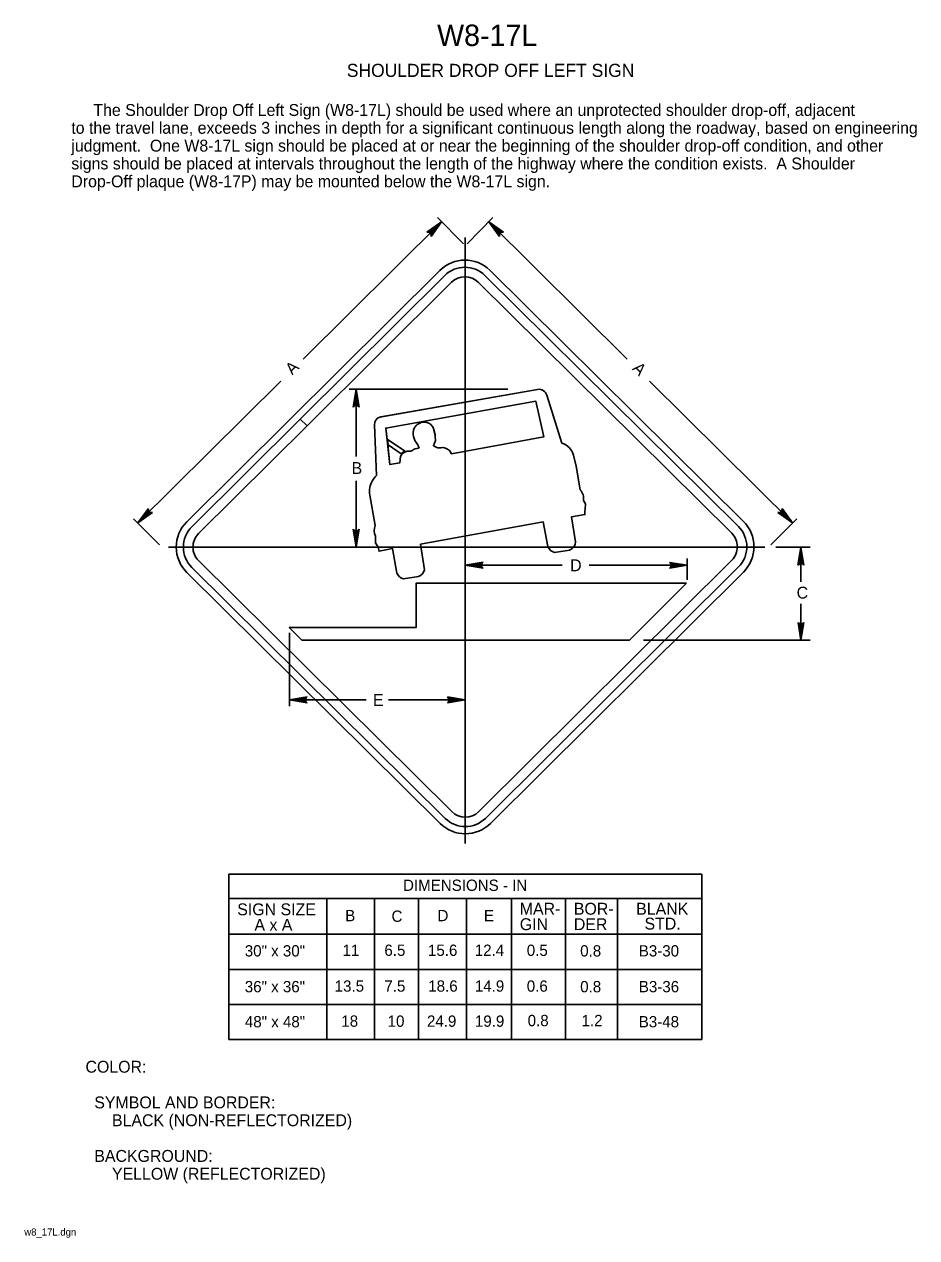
# Model space of a CAD drawing. Extents: x 0.013 to 0.2, y 0.004 to 0.259.
import ezdxf

# ---------------------------------------------------------------- set-up
doc = ezdxf.new("R2010")
doc.units = 0
for name, color, linetype in [('1', 7, 'Continuous'), ('2', 7, 'Continuous'), ('3', 7, 'Continuous')]:
    doc.layers.add(name, color=color, linetype=linetype)

# ---------------------------------------------------------------- blocks, each defined once
blk = doc.blocks.new('RARROW')
at = {"layer": '3'}
for p, q in [((-2.156, 0.28500000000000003), (-2.2665, 0.384625)), ((-2.2665, 0.384625), (0, 0)), ((0, 0), (-2.2665, -0.379125)), ((-2.156, 0.28500000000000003), (-2.075625, 0.12075)), ((0, 0), (-2.156, 0.28500000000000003)), ((-2.14975, -0.2705), (0, 0)), ((-2.075625, 0.12075), (0, 0)), ((0, 0), (-2.074, -0.108)), ((-2.2665, -0.379125), (-2.14975, -0.2705)), ((-2.074, -0.108), (-2.14975, -0.2705))]:
    blk.add_line(p, q, dxfattribs=at)

msp = doc.modelspace()

# ---------------------------------------------------------------- linework, layer by layer
at = {"layer": '1'}
for p, q in [((0.1053605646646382, 0.21425714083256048), (0.1053605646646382, 0.08680598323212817)), ((0.07068008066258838, 0.17605027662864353), (0.10107444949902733, 0.2062433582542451)), ((0.10248395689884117, 0.20482445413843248), (0.07210136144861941, 0.17464306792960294)), ((0.16141532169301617, 0.1520587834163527), (0.10811729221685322, 0.2048291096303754)), ((0.10952445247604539, 0.20625034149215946), (0.16282248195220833, 0.15348001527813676)), ((0.08742460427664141, 0.17645826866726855), (0.12056955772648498, 0.18228091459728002)), ((0.1225392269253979, 0.1810833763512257), (0.12567791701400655, 0.1710036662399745)), ((0.04786371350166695, 0.15338501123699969), (0.07068008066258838, 0.17605027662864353)), ((0.07068008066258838, 0.17605027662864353), (0.07210136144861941, 0.17464306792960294)), ((0.07210136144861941, 0.17464306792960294), (0.07068008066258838, 0.17605027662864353)), ((0.07210136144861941, 0.17464306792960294), (0.049273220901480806, 0.15196610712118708)), ((0.08667658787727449, 0.16417888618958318), (0.08630062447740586, 0.17482561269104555)), ((0.08915051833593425, 0.17063020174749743), (0.08900977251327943, 0.17178997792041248)), ((0.08900977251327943, 0.17178997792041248), (0.0927147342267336, 0.16929882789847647)), ((0.12191549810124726, 0.17232388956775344), (0.10245110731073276, 0.16876716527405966)), ((0.09190937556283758, 0.16875870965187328), (0.08915051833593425, 0.17063020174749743)), ((0.09416894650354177, 0.16939378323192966), (0.09393171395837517, 0.16930810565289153)), ((0.09532173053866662, 0.17080843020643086), (0.09564590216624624, 0.16991083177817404)), ((0.09940903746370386, 0.17006046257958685), (0.09866722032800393, 0.17043551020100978)), ((0.10245110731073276, 0.16876716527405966), (0.10204736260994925, 0.16943059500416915)), ((0.12811941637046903, 0.1684608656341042), (0.12871538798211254, 0.16614381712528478)), ((0.12871538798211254, 0.16614381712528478), (0.12954931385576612, 0.16118168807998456)), ((0.08640088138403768, 0.15367627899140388), (0.08526974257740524, 0.16007559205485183)), ((0.12178798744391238, 0.1544280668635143), (0.09593277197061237, 0.14978453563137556)), ((0.12277516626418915, 0.14925470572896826), (0.12178798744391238, 0.1544280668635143)), ((0.042952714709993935, 0.1491282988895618), (0.16834832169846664, 0.1491282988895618)), ((0.09593277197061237, 0.14978453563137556), (0.09676872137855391, 0.14432194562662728)), ((0.12727965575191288, 0.1485103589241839), (0.12417716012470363, 0.14802723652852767)), ((0.04927791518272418, 0.14628583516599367), (0.10257594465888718, 0.09351550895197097)), ((0.10820927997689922, 0.0935201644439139), (0.16142001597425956, 0.14637851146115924)), ((0.10116878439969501, 0.09209427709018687), (0.04787075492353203, 0.1448646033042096)), ((0.09551573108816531, 0.1429306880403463), (0.09241323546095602, 0.14244756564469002)), ((0.16282952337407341, 0.14495960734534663), (0.10961878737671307, 0.09210126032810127))]:
    msp.add_line(p, q, dxfattribs=at)
for points in [[(0.12056955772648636, 0.18228091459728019), (0.08762586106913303, 0.17649362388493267), (0.08762589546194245, 0.1764934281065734), (0.0876230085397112, 0.1764931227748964), (0.08742460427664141, 0.1764582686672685)], [(0.09164332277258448, 0.16687193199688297), (0.0895269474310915, 0.1665008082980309), (0.08865805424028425, 0.1741648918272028), (0.12022784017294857, 0.1797904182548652), (0.12191549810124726, 0.17232388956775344)], [(0.09177016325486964, 0.1681814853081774), (0.09164332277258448, 0.16687193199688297), (0.0895269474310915, 0.1665008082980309), (0.08905995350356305, 0.1706199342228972), (0.08892834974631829, 0.17178074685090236), (0.08865805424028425, 0.1741648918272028), (0.12022784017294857, 0.1797904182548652), (0.12191549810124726, 0.17232388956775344), (0.10245110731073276, 0.16876716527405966), (0.10204736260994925, 0.16943059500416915)], [(0.12567791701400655, 0.17100366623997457), (0.12253922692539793, 0.1810833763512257)], [(0.08630062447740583, 0.17482561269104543), (0.08667658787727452, 0.16417888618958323)], [(0.09866722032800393, 0.17043551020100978), (0.099125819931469, 0.1715678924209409), (0.0990109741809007, 0.1723614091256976), (0.09907033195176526, 0.17273816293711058), (0.0987450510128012, 0.1739024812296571)], [(0.09940903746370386, 0.1700604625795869), (0.09866722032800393, 0.17043551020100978), (0.099125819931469, 0.1715678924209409), (0.0990109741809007, 0.1723614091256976), (0.09907033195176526, 0.17273816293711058), (0.09886476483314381, 0.17347397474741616), (0.0987450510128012, 0.1739024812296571)], [(0.09271473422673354, 0.16929882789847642), (0.08900977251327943, 0.17178997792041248), (0.08915051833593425, 0.17063020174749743), (0.09190937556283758, 0.16875870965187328)], [(0.0941689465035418, 0.16939378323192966), (0.09393171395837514, 0.16930810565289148)], [(0.09532173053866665, 0.1708084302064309), (0.09564590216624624, 0.16991083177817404)], [(0.12954931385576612, 0.16118168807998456), (0.12871538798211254, 0.16614381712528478), (0.12811941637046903, 0.1684608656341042)], [(0.09177016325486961, 0.1681814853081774), (0.09164174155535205, 0.1668809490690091)], [(0.08526974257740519, 0.16007559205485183), (0.08640088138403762, 0.15367627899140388)], [(0.13026041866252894, 0.15891250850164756), (0.1306328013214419, 0.15822212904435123), (0.13060219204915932, 0.15710398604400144), (0.13049077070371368, 0.15672384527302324), (0.13052973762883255, 0.1559680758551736), (0.1276898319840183, 0.1554732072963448), (0.1285725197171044, 0.1502112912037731)], [(0.12857251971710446, 0.15021129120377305), (0.1276898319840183, 0.1554732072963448), (0.13052973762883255, 0.1559680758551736), (0.13049077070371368, 0.15672384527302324), (0.13060219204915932, 0.15710398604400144), (0.1306328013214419, 0.15822212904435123), (0.13026041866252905, 0.15891250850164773)], [(0.09593277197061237, 0.14978453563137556), (0.12178798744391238, 0.1544280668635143), (0.12277516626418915, 0.1492547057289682)], [(0.09101124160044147, 0.1436750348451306), (0.09008030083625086, 0.14882559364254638), (0.08725567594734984, 0.1482498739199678), (0.08707744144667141, 0.14912433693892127), (0.0864759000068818, 0.15004057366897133), (0.0864759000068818, 0.15145183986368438)], [(0.0864759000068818, 0.15145183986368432), (0.0864759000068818, 0.15004057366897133), (0.08707744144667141, 0.14912433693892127), (0.08725567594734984, 0.1482498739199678), (0.09008030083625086, 0.14882559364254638), (0.0910112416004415, 0.1436750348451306)], [(0.09676872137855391, 0.14432194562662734), (0.09593277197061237, 0.14978453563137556)], [(0.12417716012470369, 0.14802723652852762), (0.12727965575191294, 0.14851035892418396)], [(0.09241323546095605, 0.14244756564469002), (0.09551573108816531, 0.14293068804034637)], [(0.1518832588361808, 0.14154188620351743), (0.09502367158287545, 0.14154188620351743), (0.09502367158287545, 0.1322096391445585), (0.06836508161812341, 0.1322096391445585), (0.07102188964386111, 0.129568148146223), (0.13991300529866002, 0.12957093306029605), (0.1518832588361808, 0.14154188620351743)], [(0.1518832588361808, 0.14154188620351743), (0.13991300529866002, 0.12957093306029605), (0.07102188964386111, 0.129568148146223), (0.06836508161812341, 0.1322096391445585), (0.09502367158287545, 0.1322096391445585), (0.09502367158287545, 0.14154188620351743), (0.1518832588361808, 0.14154188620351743)]]:
    msp.add_lwpolyline(points, dxfattribs=at)
for centre, radius, start, end in [((0.10530297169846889, 0.20198664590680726), 0.005999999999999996, 45.285051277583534, 134.8096492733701), ((0.10530297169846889, 0.20198664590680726), 0.004000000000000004, 45.285051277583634, 134.80964927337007), ((0.12087692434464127, 0.18056786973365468), 0.0017404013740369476, 17.229499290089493, 100.17217419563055), ((0.12087692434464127, 0.18056786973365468), 0.0017404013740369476, 17.229499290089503, 100.17217419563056), ((0.08778138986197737, 0.1750094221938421), 0.0014921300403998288, 103.83411158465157, 187.07601051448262), ((0.08778138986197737, 0.1750094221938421), 0.0014921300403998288, 103.83411158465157, 187.07601051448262), ((0.09752020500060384, 0.17299703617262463), 0.003102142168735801, 158.1835378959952, 224.87111651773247), ((0.09752020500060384, 0.17299703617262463), 0.0031021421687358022, 158.1835378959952, 224.87111651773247), ((0.09678454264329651, 0.17298383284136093), 0.002440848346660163, 90.66413138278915, 151.46274562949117), ((0.09678454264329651, 0.17298383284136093), 0.002440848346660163, 90.66413138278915, 151.46274562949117), ((0.09666928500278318, 0.17316791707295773), 0.0022582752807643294, 36.5300670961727, 87.79300552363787), ((0.09666928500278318, 0.17316791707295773), 0.0022582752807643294, 36.5300670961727, 87.79300552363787), ((0.09477268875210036, 0.17256172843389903), 0.004192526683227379, 12.567443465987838, 27.72395795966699), ((0.09477268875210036, 0.17256172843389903), 0.004192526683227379, 18.650581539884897, 27.723957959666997), ((0.12457428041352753, 0.16750047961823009), 0.0036729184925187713, 15.15775744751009, 72.51359655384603), ((0.12457428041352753, 0.16750047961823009), 0.003672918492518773, 15.157757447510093, 72.51359655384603), ((0.09307092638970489, 0.16780186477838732), 0.0013550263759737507, 118.82030868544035, 163.73040696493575), ((0.09307092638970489, 0.16780186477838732), 0.0013550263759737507, 118.82030868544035, 163.73040696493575), ((0.09307092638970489, 0.16780186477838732), 0.001504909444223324, 118.90139087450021, 140.51949909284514), ((0.09307092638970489, 0.16780186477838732), 0.001504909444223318, 118.90139087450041, 140.5194990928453), ((0.093650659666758, 0.16689009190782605), 0.002584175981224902, 111.23386621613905, 120.38409399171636), ((0.093650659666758, 0.16689009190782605), 0.002584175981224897, 111.2338662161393, 120.3840939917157), ((0.093650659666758, 0.16689009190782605), 0.0024342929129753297, 83.37005939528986, 120.43025837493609), ((0.093650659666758, 0.16689009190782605), 0.0024342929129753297, 83.37005939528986, 120.43025837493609), ((0.09555652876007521, 0.16779813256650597), 0.0021145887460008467, 87.57766385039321, 131.01031243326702), ((0.09555652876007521, 0.16779813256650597), 0.0021145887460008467, 87.57766385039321, 131.01031243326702), ((0.09989996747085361, 0.17159391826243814), 0.0016101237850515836, 252.24773023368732, 282.30135138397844), ((0.09989996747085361, 0.17159391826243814), 0.0016101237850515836, 252.24773023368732, 282.30135138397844), ((0.10059116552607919, 0.16803183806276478), 0.0020191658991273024, 43.84739517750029, 102.03392138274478), ((0.10059116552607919, 0.16803183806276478), 0.0020191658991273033, 43.84739517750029, 99.92887190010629), ((0.0896948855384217, 0.16092984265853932), 0.004434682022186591, 132.89148295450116, 170.84487329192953), ((0.0896948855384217, 0.16092984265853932), 0.0044346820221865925, 132.89148295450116, 170.84487329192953), ((0.09084512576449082, 0.16068839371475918), 0.005608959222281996, 170.27935181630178, 186.27231814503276), ((0.09084512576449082, 0.16068839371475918), 0.005608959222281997, 170.27935181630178, 186.27231814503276), ((0.1272505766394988, 0.15921530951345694), 0.003025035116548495, 354.2551662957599, 40.544237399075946), ((0.1272505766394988, 0.15921530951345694), 0.0030250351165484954, 354.25516629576, 40.54423739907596), ((0.05209223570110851, 0.14912829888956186), 0.006000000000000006, 134.80964927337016, 225.28505127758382), ((0.08924969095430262, 0.1526588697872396), 0.0030250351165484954, 160.34658236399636, 203.51652360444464), ((0.08924969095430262, 0.1526588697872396), 0.0030250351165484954, 160.34658236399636, 203.51652360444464), ((0.15860100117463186, 0.1492163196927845), 0.006000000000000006, 314.8096492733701, 45.285051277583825), ((0.05209223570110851, 0.14912829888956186), 0.004000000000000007, 134.80964927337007, 225.28505127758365), ((0.15860100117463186, 0.1492163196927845), 0.0040000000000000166, 314.8096492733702, 45.28505127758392), ((0.12454343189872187, 0.14985998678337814), 0.0018689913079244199, 198.8961834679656, 258.6984327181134), ((0.12454343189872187, 0.14985998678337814), 0.00186899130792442, 198.8961834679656, 258.6984327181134), ((0.12669647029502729, 0.1502954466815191), 0.0018779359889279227, 288.09213636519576, 357.4315583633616), ((0.12669647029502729, 0.1502954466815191), 0.0018779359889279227, 288.09213636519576, 357.4315583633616), ((0.09277950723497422, 0.14428031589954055), 0.0018689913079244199, 198.8961834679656, 258.6984327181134), ((0.09277950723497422, 0.14428031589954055), 0.00186899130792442, 198.8961834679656, 258.6984327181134), ((0.09493254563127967, 0.1447157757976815), 0.0018779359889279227, 288.09213636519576, 347.89438561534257), ((0.09493254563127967, 0.1447157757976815), 0.0018779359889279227, 288.09213636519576, 347.89438561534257), ((0.1053902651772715, 0.09635797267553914), 0.006000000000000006, 225.28505127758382, 314.8096492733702), ((0.1053902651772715, 0.09635797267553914), 0.003999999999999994, 225.28505127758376, 314.8096492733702)]:
    msp.add_arc(centre, radius, start, end, dxfattribs=at)
at = {"layer": '3'}
for p, q in [((0.0712652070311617, 0.18866258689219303), (0.10039481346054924, 0.21753592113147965)), ((0.10497065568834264, 0.2129194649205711), (0.09951484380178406, 0.21842370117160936)), ((0.10575047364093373, 0.2129194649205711), (0.11120628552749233, 0.21842370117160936)), ((0.13945592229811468, 0.18866258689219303), (0.11032631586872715, 0.21753592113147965)), ((0.04680658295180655, 0.15444918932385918), (0.10001731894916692, 0.2073075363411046)), ((0.1105798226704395, 0.20731626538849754), (0.16387785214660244, 0.15454593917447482)), ((0.06661774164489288, 0.18405600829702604), (0.0365011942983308, 0.15420441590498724)), ((0.14410338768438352, 0.18405600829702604), (0.17421993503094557, 0.15420441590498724)), ((0.08096905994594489, 0.1823108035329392), (0.11436272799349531, 0.1823108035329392)), ((0.08243096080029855, 0.168166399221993), (0.08243096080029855, 0.18231080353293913)), ((0.08243096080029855, 0.16307330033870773), (0.08243096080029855, 0.14913548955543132)), ((0.04107703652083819, 0.1495879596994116), (0.035621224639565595, 0.15509219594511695)), ((0.1696440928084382, 0.1495879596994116), (0.1750999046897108, 0.15509219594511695)), ((0.17072446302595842, 0.1491282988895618), (0.1779116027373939, 0.1491282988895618)), ((0.17597973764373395, 0.14181023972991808), (0.17597973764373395, 0.14907355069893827)), ((0.15207602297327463, 0.14224655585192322), (0.15207602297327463, 0.14671242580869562)), ((0.046815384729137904, 0.14379867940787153), (0.1001134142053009, 0.09102835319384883)), ((0.12575947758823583, 0.14530743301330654), (0.10538708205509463, 0.14530743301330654)), ((0.11067591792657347, 0.09103708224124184), (0.16388665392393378, 0.1438954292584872)), ((0.13142962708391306, 0.14530743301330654), (0.15207602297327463, 0.14530743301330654)), ((0.17597973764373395, 0.13721892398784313), (0.17597973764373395, 0.1295541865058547)), ((0.06837785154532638, 0.11570222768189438), (0.06837785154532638, 0.13111637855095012)), ((0.14284362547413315, 0.129568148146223), (0.1779116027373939, 0.129568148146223)), ((0.0845332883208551, 0.11700686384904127), (0.06837785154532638, 0.11700686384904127)), ((0.08922496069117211, 0.11700686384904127), (0.10535728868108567, 0.11700686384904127)), ((0.05561963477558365, 0.08034473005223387), (0.15510740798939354, 0.08034473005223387)), ((0.05561963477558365, 0.08034473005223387), (0.05561963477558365, 0.045594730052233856)), ((0.15510740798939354, 0.08034473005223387), (0.15510740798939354, 0.045594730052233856)), ((0.15510740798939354, 0.07521867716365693), (0.05561963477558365, 0.07521867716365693)), ((0.07624242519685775, 0.07521867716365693), (0.07624242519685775, 0.045594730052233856)), ((0.0955585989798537, 0.07521867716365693), (0.0955585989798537, 0.045594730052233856)), ((0.12649030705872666, 0.07521867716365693), (0.12649030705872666, 0.045594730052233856)), ((0.13742347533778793, 0.07521867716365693), (0.13742347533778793, 0.045594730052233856)), ((0.05561963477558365, 0.06771973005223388), (0.15510740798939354, 0.06771973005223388)), ((0.055633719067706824, 0.060344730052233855), (0.15510740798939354, 0.060344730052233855)), ((0.055647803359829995, 0.052969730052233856), (0.15510740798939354, 0.052969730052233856)), ((0.055633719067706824, 0.045594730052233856), (0.15510740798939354, 0.045594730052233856))]:
    msp.add_line(p, q, dxfattribs=at)
for points in [[(0.08626963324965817, 0.07521867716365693), (0.08626963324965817, 0.045594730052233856)], [(0.10566226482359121, 0.07521867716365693), (0.10566226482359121, 0.045594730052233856)], [(0.11510535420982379, 0.07521867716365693), (0.11510535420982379, 0.045594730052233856)]]:
    msp.add_lwpolyline(points, dxfattribs=at)
for centre, start, end in [((0.10530297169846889, 0.20198664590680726), 45.285051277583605, 134.80964927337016), ((0.05209223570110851, 0.14912829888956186), 134.80964927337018, 225.28505127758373), ((0.15860100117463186, 0.1492163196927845), 314.8096492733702, 45.28505127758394), ((0.1053902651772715, 0.09635797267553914), 225.2850512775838, 314.80964927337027)]:
    msp.add_arc(centre, 0.0075, start, end, dxfattribs=at)

# ---------------------------------------------------------------- block references
for p, xscale, yscale, rotation in [((0.10039481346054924, 0.21753592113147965), 0.0016545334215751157, 0.0016366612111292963, 44.74685388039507), ((0.11032631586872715, 0.21753592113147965), 0.0016545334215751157, -0.0016366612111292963, 135.25314611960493), ((0.08243096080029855, 0.18231080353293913), 0.0016545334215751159, 0.0016366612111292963, 90), ((0.0365011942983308, 0.15420441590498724), 0.001654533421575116, 0.0016366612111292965, -135.25314611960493), ((0.17421993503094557, 0.15420441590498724), 0.001654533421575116, -0.0016366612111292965, -44.74685388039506), ((0.08243096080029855, 0.14913548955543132), 0.0016545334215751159, 0.0016366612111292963, -90), ((0.17597973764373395, 0.14907355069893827), 0.0016545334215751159, 0.0016366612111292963, 90), ((0.10538708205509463, 0.14530743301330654), 0.0016545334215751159, -0.0016366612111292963, 180), ((0.17597973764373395, 0.1295541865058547), 0.0016545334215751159, 0.0016366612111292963, -90), ((0.06837785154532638, 0.11700686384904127), 0.0016545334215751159, -0.0016366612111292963, 180)]:
    msp.add_blockref('RARROW', p, dxfattribs=dict(at, xscale=xscale, yscale=yscale, rotation=rotation))
at = {"layer": '3', "xscale": 0.0016545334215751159, "yscale": -0.0016366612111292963}
for p in [(0.15207602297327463, 0.14530743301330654), (0.10535728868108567, 0.11700686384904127)]:
    msp.add_blockref('RARROW', p, dxfattribs=at)

# ---------------------------------------------------------------- texts
at = {"layer": '1'}
for s, height, p in [('W8-17L', 0.0045000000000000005, (0.09945, 0.2545)), ('SHOULDER DROP OFF LEFT SIGN', 0.00275025, (0.08045761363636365, 0.248)), ('COLOR:', 0.0024997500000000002, (0.025500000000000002, 0.038624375)), ('  SYMBOL AND BORDER:', 0.0024997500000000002, (0.025500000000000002, 0.031124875)), ('      BLACK (NON-REFLECTORIZED)', 0.0024997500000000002, (0.025500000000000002, 0.027375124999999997)), ('  BACKGROUND:', 0.0024997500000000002, (0.025500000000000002, 0.019875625)), ('      YELLOW (REFLECTORIZED)', 0.0024997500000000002, (0.025500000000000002, 0.016125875)), ('w8_17L.dgn', 0.0015, (0.012625, 0.004375))]:
    msp.add_text(s, height=height, dxfattribs=at).set_placement(p)
at = {"layer": '2'}
for s, p in [('     The Shoulder Drop Off Left Sign (W8-17L) should be used where an unprotected shoulder drop-off, adjacent', (0.02251589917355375, 0.23979256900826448)), ('to the travel lane, exceeds 3 inches in depth for a significant continuous length along the roadway, based on engineering', (0.02251589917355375, 0.2360428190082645)), ('judgment.  One W8-17L sign should be placed at or near the beginning of the shoulder drop-off condition, and other', (0.02251589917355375, 0.2322930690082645)), ('signs should be placed at intervals throughout the length of the highway where the condition exists.  A Shoulder ', (0.02251589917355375, 0.2285433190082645)), ('Drop-Off plaque (W8-17P) may be mounted below the W8-17L sign.', (0.02251589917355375, 0.2247935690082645))]:
    msp.add_text(s, height=0.0024997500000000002, dxfattribs=at).set_placement(p)
at = {"layer": '3'}
for s, height, rotation, p in [('A', 0.0025, 44.746853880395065, (0.06900583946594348, 0.18518931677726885)), ('A', 0.0025, 315.25314611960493, (0.14035725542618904, 0.18653540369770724)), ('B', 0.0024997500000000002, 360, (0.0814670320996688, 0.16450338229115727)), ('D', 0.0025, 360, (0.12743203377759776, 0.14405743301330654)), ('C', 0.0024997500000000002, 360, (0.17506631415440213, 0.13831000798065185)), ('E', 0.0025, 360, (0.08596761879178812, 0.11575686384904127)), ('DIMENSIONS - IN', 0.0023752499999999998, 360, (0.09228785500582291, 0.07684473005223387)), ('E', 0.0023752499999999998, 360, (0.1092986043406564, 0.07046973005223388)), ('15.6', 0.0023752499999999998, 360, (0.09752745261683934, 0.063182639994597)), ('18.6', 0.0023752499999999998, 360, (0.09759158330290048, 0.05565589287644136)), ('24.9', 0.0023752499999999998, 360, (0.09731806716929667, 0.04828089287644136)), ('0.8', 0.0023752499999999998, 360, (0.11849678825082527, 0.04840589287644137))]:
    msp.add_text(s, height=height, rotation=rotation, dxfattribs=at).set_placement(p)
for s, height, p in [('SIGN SIZE', 0.0024997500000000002, (0.05742012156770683, 0.07171973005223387)), ('MAR-', 0.0024997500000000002, (0.11683816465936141, 0.07184473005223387)), ('BOR-', 0.0024997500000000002, (0.12821316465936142, 0.07184473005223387)), ('BLANK', 0.0024997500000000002, (0.141324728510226, 0.07184473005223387)), ('B', 0.0023752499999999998, (0.08012681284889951, 0.07046973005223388)), ('C', 0.0023752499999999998, (0.08987011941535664, 0.07033951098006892)), ('D', 0.0023752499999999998, (0.09953417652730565, 0.07046973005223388)), ('A x A', 0.0024997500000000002, (0.06103188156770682, 0.06846998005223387)), ('GIN', 0.0024997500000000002, (0.11683816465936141, 0.06859473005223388)), ('DER', 0.0024997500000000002, (0.12821316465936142, 0.06859473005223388)), ('STD.', 0.0024997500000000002, (0.143074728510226, 0.06871973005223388)), ('30" x 30"', 0.0023752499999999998, (0.05900413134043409, 0.063057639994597)), ('11', 0.0023752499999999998, (0.07955789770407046, 0.063182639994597)), ('6.5', 0.0023752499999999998, (0.08836201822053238, 0.063182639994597)), ('12.4', 0.0023752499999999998, (0.10737538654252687, 0.063182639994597)), ('0.5', 0.0023752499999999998, (0.11831367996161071, 0.06317742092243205)), ('0.8', 0.0023752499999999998, (0.1295478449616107, 0.06305242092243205)), ('B3-30', 0.0023752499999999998, (0.14186984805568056, 0.063057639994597)), ('36" x 36"', 0.0023752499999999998, (0.05900413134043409, 0.05553089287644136)), ('13.5', 0.0023752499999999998, (0.07791033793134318, 0.05565589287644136)), ('7.5', 0.0023752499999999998, (0.08836201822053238, 0.05565589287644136)), ('14.9', 0.0023752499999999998, (0.1073905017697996, 0.05565589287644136)), ('0.6', 0.0023752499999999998, (0.11831080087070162, 0.055650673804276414)), ('0.8', 0.0023752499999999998, (0.1295478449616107, 0.055525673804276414)), ('B3-36', 0.0023752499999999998, (0.14187488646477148, 0.05553089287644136)), ('48" x 48"', 0.0023752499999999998, (0.05901821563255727, 0.04815589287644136)), ('18', 0.0023752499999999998, (0.07931214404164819, 0.04828089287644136)), ('10', 0.0023752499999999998, (0.08905196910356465, 0.04828089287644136)), ('19.9', 0.0023752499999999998, (0.10740458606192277, 0.04828089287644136)), ('1.2', 0.0023752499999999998, (0.1298422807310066, 0.04840589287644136)), ('B3-48', 0.0023752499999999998, (0.14186193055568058, 0.04815589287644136))]:
    msp.add_text(s, height=height, dxfattribs=at).set_placement(p)

doc.saveas('drawing.dxf')
